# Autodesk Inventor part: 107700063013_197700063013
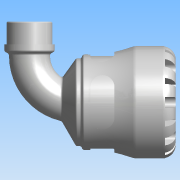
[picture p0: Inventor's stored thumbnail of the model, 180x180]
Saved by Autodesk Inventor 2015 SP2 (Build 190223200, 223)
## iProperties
Created: 2016-12
Part Number: 107700063013_197700063013
Material: PVC-Piping
Description: PLASSON 90° ELBOW WITH MALE INTEGRAL BRASS 63X1.1/4" SERIES 1
Document SubType Name: Modeling
Designer: KIM
Mass: 664.223 g
Surface Area: 733.008 cm^2
Volume: 474.445 cm^3
Density: 1.4 g/cm^3
Appearance: Smooth - White
Author: KIM
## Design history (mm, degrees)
derived "1077.ipt"
feature "Solid1::1077.ipt"
tag "TaggingFeature1"
body "Solid1"
other parameters: "d1" = 37.8, "d2" = 63, "d3" = 78.75, "d4" = 103, "d8" = 87.55, "d13" = 9.7, "d14" = 9.7, "d15" = 0, "d17" = 360 deg, "d19" = 8 deg, "d20" = 1.26, "d21" = 1.26, "d22" = 8 deg, "d24" = 0, "d26" = 360 deg, "d33" = 10.3, "d43" = 80.34, "d51" = 1.03, "d54" = 22.05, "d55" = 13.86, "d57" = 19.012, "d58" = 0, "d74" = 0, "d82" = 1.26, "d115" = 360 deg, "d207" = 90 deg, "d228" = 18.7425, "d247" = 2.06, "d248" = 5.4, "d268" = 48.1525, "d269" = 5.4, "d270" = 134, "d276" = 41.91, "d277" = 21, "d278" = 46.101, "d279" = 74, "d280" = 27.3, "d281" = 6.2865, "d283" = 37.719, "d286" = 0, "d287" = 0, "d288" = 29.337, "d290" = 21.3105, "d292" = 30 deg, "d294" = 4.191, "d296" = 30 deg, "d_" = 63, "E_" = 103, "A_" = 134, "A_1" = 74, "l_2" = 21, "R_" = 41.91, "d9" = 12.125, "d11" = 103, "d12" = 78.75, "d289" = 29.337
